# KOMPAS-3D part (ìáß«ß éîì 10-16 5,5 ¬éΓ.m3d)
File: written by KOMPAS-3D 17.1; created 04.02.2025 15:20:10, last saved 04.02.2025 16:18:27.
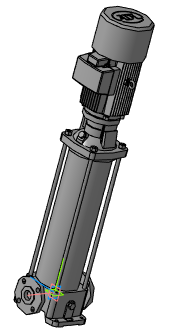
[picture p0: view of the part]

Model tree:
1. Операция без истории:1  (labels: Насос ВМН 10-16 5,5 кВт)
